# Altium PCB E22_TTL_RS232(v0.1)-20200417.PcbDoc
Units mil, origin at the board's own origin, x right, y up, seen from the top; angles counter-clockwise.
Board outline 1576 x 2223 mil, 2 copper layers (TopLayer, BottomLayer); 30 components, 23 nets, 110 pads, 426 vias.
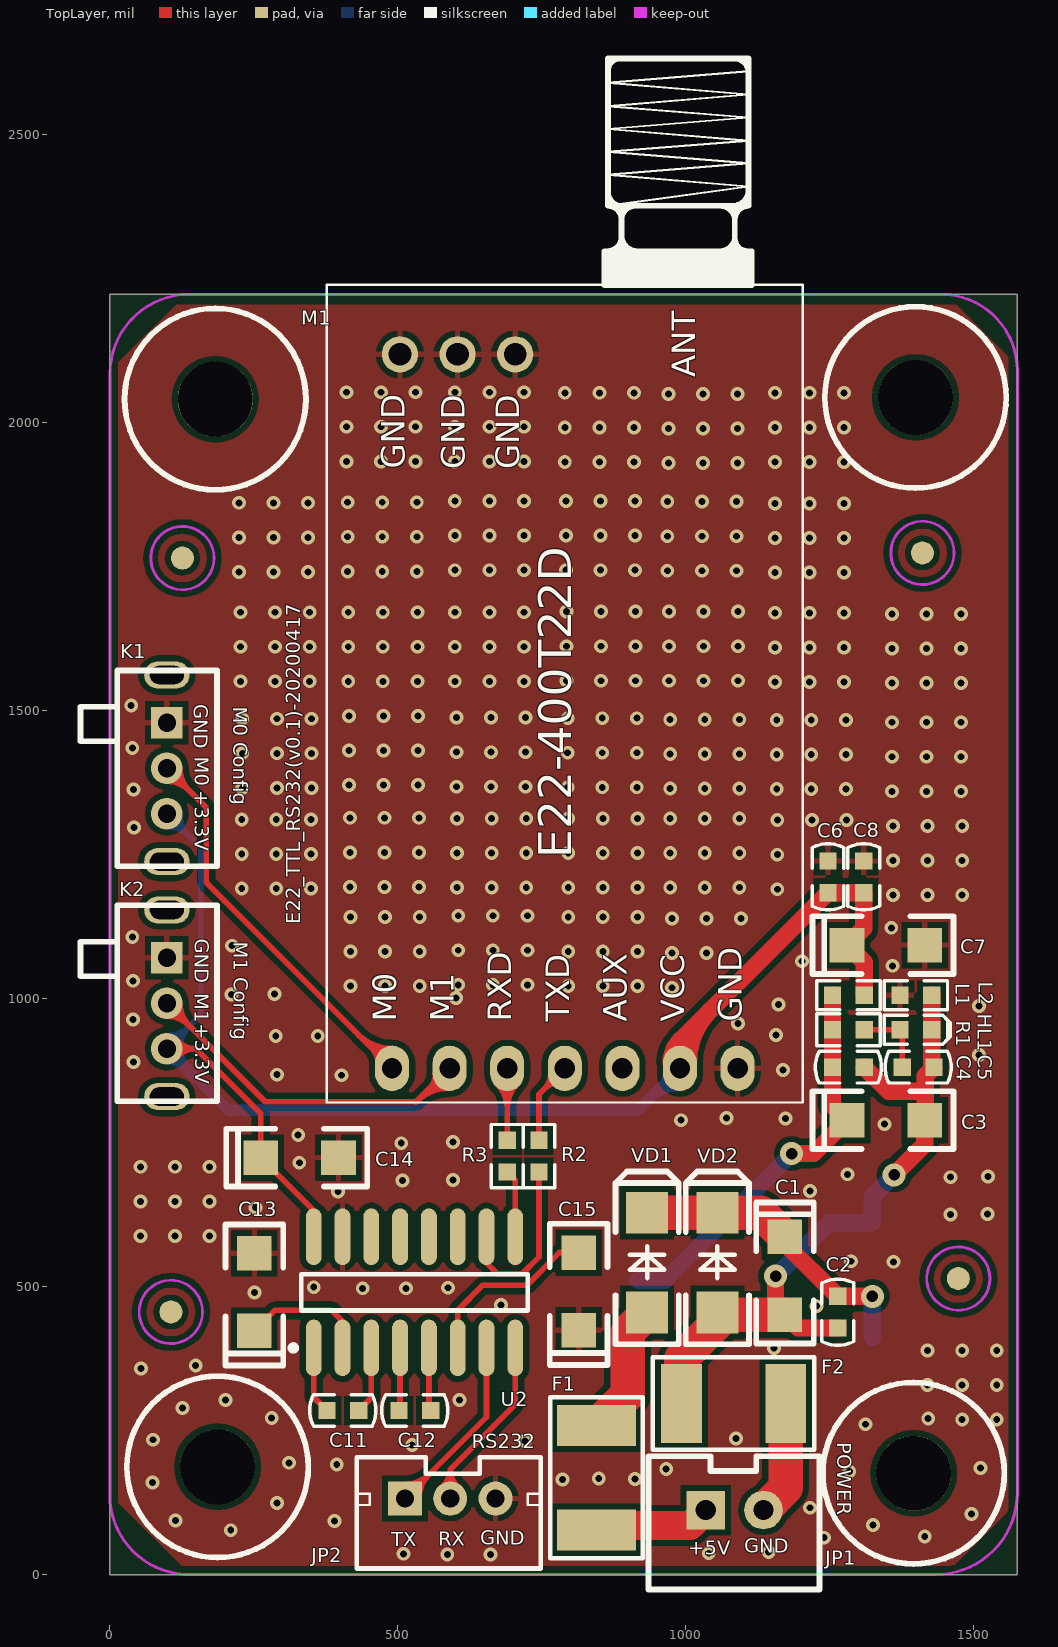
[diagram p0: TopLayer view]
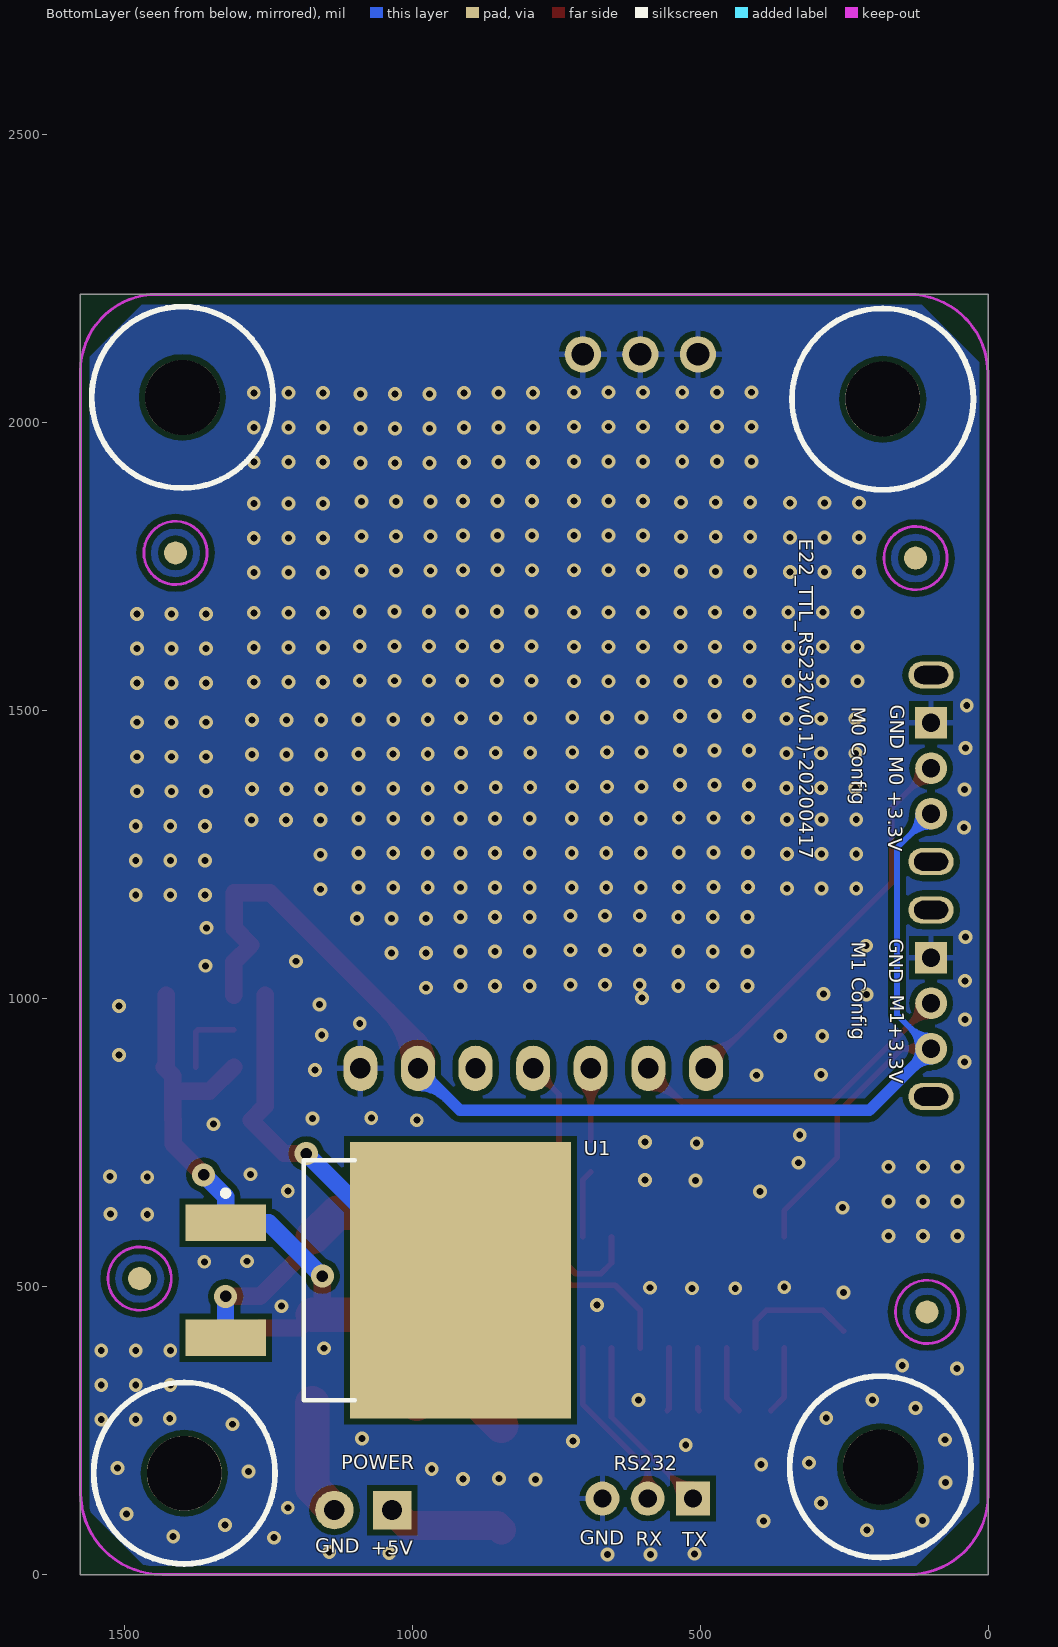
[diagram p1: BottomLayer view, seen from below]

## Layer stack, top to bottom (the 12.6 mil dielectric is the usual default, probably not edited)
TopLayer: signal copper 1.4
Dielectric: core 12.6, FR-4, Dk 4.8
BottomLayer: signal copper 1.4

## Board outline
0,0 1575,0 1576,0 1576,2221 1576,2223 0,2223 0,0

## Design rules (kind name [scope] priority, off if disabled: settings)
Clearance Clearance_2 [InNet('RF_IN') vs InNet('GND')] p1: gap=19.68
Clearance [All] p2: gap=10
Clearance Clearance_1 [All] p3: gap=10
ComponentClearance [All] p1 off: gap=10 collisioncheckmode=3 verticalgap=10 showdistances=FALSE
FabricationTestPointUsage TestPointUsage [All] p1: valid=0 allowmultiple=FALSE
FabricationTestpoint Testpoint [(IsPad And (OnTopLayer Or OnBottomLayer))] p1: side=3 testpointundercomponent=TRUE minsize=40 maxsize=100 preferedsize=60 minholesize=20 maxholesize=40 preferedholesize=32 testpointgrid=1 allowsidetop=TRUE allowsidebottom=TRUE usegrid=TRUE gridtolerance=0.01
HoleSize [All] p1: absolutevalues=TRUE maxlimit=200 minlimit=1 maxpercent=80.000 minpercent=20.000
PolygonConnect [IsVia] p1: connectstyle=Direct reliefconductorwidth=10 reliefentries=4 polygonreliefangle="90 Angle"
PolygonConnect PolygonConnect_via [All] p2 off: connectstyle=Relief reliefconductorwidth=10 reliefentries=4 polygonreliefangle="90 Angle"
RoomDefinition E22_TTL_RS232(v0.1)-20200417 [InComponentClass('E22_TTL_RS232(v0.1)-20200417')] p1: confinementstyle=ConfineIn formatcopy=TRUE lockcomponents=FALSE outline -14648,-34893 -12648,-34893 -12648,-33893 -14648,-33893
RoutingVias [All] p1: holewidth=15.75 width=31.5 viastyle="Through Hole" minholewidth=11.81 minwidth=23.62 maxholewidth=19.68 maxwidth=39.37
ShortCircuit [All] p1 off: allowed=FALSE
SilkscreenOverComponentPads [All] p1: minsilkscreentomaskgap=10
SolderMaskExpansion [All] p1: expansion=4
Width [All] p1: maxlimit=100 minlimit=5 preferedwidth=10
22 further rules are at their usual default settings.

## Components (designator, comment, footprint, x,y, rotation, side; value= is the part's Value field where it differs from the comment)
C1 "10uF/25V/5%" C1206-1 1172.23,586.23 r270 top
C2 "100nF/25V/5%" C0603 1264,428 r90 top
C3 "10uF/25V/5%" C1206-1 1280,789 r0 top
C4 "100nF/25V/5%" C0603 1310,881 r180 top
C5 "100nF/25V/5%" C0603 1376,881 r0 top
C6 "100nF/25V/5%" C0603 1247,1239 r270 top
C7 "10uF/25V/5%" C1206-1 1280,1093 r0 top
C8 "100nF/25V/5%" C0603 1309,1239 r270 top
C11 "100nF/25V/5%" C0603 432,285 r180 top
C12 "100nF/25V/5%" C0603 502,285 r0 top
C13 "100nF/25V/5%" C1206-1 251,423 r90 top
C14 "100nF/25V/5%" C1206-1 262,724 r0 top
C15 "100nF/25V/5%" C1206-1 814,424 r90 top
F1 "6V/500mA" F1812 845,168 r90 top
F2 "6V/500mA" F1812 1083,297 r180 top
HL1 "LED蓝灯" LED0603 1372,946 r0 top
JP1 "供电电源" XH2.54-LI-2P 1085,112 r0 top
JP2 "RS232串口" PH2.0-LI-3P 591,132 r0 top locked
K1 "M0选择" SK-12D07 99,1400 r270 top locked
K2 "M1选择" SK-12D07 99,992 r270 top locked
L1 "10uH/5%" L0603 1255,1006 r0 top
L2 "10uH/5%" L0603 1427,1006 r180 top
M1 "E22-400T22D" E22-400T22D 490,879 r90 top locked
R1 "2K/5%" R0603 1255,946 r0 top
R2 "33R/5%" R0603 745,699 r90 top
R3 "33R/5%" R0603 690,699 r90 top
U1 "AMS1117-3.3" D2PAK 1070,511 r180 bottom
U2 "MAX3232CSE" NSO16_M 529,490 r90 top
VD1 "1N5408" SMA_DO-214AC 933,455 r90 top
VD2 "1N4007" SMA_DO-214AC 1055,455 r90 top

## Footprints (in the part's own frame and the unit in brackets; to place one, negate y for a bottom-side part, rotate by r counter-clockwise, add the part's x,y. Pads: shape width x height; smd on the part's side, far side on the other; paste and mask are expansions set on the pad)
C0603 [mil]
  rect 30x30 smd: 1(0,0) 2(55,0)
  silkscreen extent -30,-28 85,28
C1206-1 [mil] "C1206封装钽电容"
  rect 60x60 smd: 1(0,0) 2(135,0)
  silkscreen extent -60,-50 185,50
D2PAK [mm] "D2-PAK, 3-Pads, Body 9.0x10.6mm (max), IPC Medium Density"
  rect 3.55x1.6 smd: 1(-6.45,2.54) 3(-6.45,-2.54)
  rect 9.75x12.2 smd: 2(3.9,0)
  silkscreen extent -6.58,-5.3 -0.75,5.3, body extent -3,-5.28 6,5.28, height 4.56
E22-400T22D [mm]
  oval 2x1.5 hole 0.9: 1(0,0) 2(0,-2.54) 3(0,-5.08) 4(0,-7.62) 5(0,-10.16) 6(0,-12.7) 7(0,-15.24)
  round 1.6 hole 1: 8(31.49,-5.43) 9(31.49,-2.89) 10(31.49,-0.35)
  silkscreen extent -1.51,-18.12 44.54,2.88
F1812 [mm]
  rect 1.8x3.5 smd: 1(-2.3,0) 2(2.3,0)
  silkscreen extent -3.56,-2.03 3.56,2.03
L0603 [mil] "L0603封装电感"
  rect 30x30 smd: 1(0,0) 2(55,0)
  silkscreen extent -28,-25 82,25
LED0603 [mil]
  rect 30x30 smd: A(0,0) K(55,0)
  silkscreen extent -28,-25 87,25
NSO16_M [mm] "SOIC, 16-Leads, Body 9.9x3.9mm, Pitch 1.27mm, IPC Low Density"
  oval 2.5x0.7 smd: 1(-2.45,4.445) 2(-2.45,3.175) 3(-2.45,1.905) 4(-2.45,0.635) 5(-2.45,-0.635) 6(-2.45,-1.905) 7(-2.45,-3.175) 8(-2.45,-4.445) 9(2.45,-4.445) 10(2.45,-3.175) 11(2.45,-1.905) 12(2.45,-0.635) 13(2.45,0.635) 14(2.45,1.905) 15(2.45,3.175) 16(2.45,4.445)
  silkscreen extent -2.57,-5 0.8,5.47, body extent -2,-5 2,5, height 1.75
PH2.0-LI-3P [mm]
  rect 1.5x1.5 hole 0.8: 1(-2,0)
  round 1.5 hole 0.8: 2(0,0) 3(2,0)
  silkscreen extent -4.13,-3.08 4,1.82, body extent -3.95,-3 3.95,1.7, height 6.01
R0603 [mil]
  rect 30x30 smd: 1(0,0) 2(55,0)
  silkscreen extent -28,-28 82,28
SK-12D07 [mm] "3脚2档小型拨动开关"
  oval 1.2x2 hole 0.8 slot 1.5 at 90 deg: 0(-4.115,0) 0(4.115,0)
  rect 1.4x1.4 hole 0.8: 1(-2.007,0)
  round 1.4 hole 0.8: 2(0,0) 3(2.007,0)
  silkscreen extent -4.32,-3.81 4.32,2.21
SMA_DO-214AC [mm]
  rect 1.85x1.85 smd: A(0,0) K(4.4,0)
  silkscreen extent -1.4,-1.4 6.22,1.4
XH2.54-LI-2P [mm]
  rect 1.7x1.7 hole 0.9: 1(-1.27,0)
  round 1.7 hole 0.9: 2(1.27,0)
  silkscreen extent -3.81,-3.51 3.74,2.37, body extent -3.77,-3.3 3.77,2.4, height 7.05

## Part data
C1 C3: library part "Cap Pol1", "钽电容"
C2 C4: library part Cap, "电容"
C5 C6: library part CAP, "电容"
C7 C13 C14 C15: library part ELECTRO1, "钽电容"
C8 C11 C12: library part CAP-SMD, "电容"
F1 F2: library part 保险丝, "自恢复保险丝"
HL1: library part 发光二极管, "发光二极管"
JP1: library part XH2.54-2P/PH2.0-2P, "XH2.54-2P/PH2.0-2P插座"
JP2: library part XH2.54-3P/PH2.0-3P, "PH2.0-3P直插插座"
K1 K2: library part SK-12D07, "SK-12D07：3脚2档小型拨动开关"
L1 L2: library part 电感, "电感"
M1: "E22-400T22D LoRa模块"
R1 R2 R3: library part RES2, "电阻"
U1: library part U_AMS1117, "U_AMS1117稳压芯片"
U2: library part MAX232CSE, "+5V Powered, Multi-Channel RS-232 Driver/Receiver"
VD1 VD2: library part 开关二极管, "开关二极管"

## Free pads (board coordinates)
  round 40 smd far side: 0(106,456) 0(126,1765) 0(1411,1774) 0(1473.31,513.95)
  round 129.92 hole 129.92: 0(183,2041) 0(187.01,187.01) 0(1395.68,176.01) 0(1399,2044)
  round 40 smd: 1(106,456) 1(126,1765) 1(1411,1774) 1(1473.31,513.95)
  round 100 on Bottom Solder: 2(106,456) 2(126,1765) 2(1411,1774) 2(1473.31,513.95)
  round 100 on Top Solder: 3(106,456) 3(126,1765) 3(1411,1774) 3(1473.31,513.95)

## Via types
v1: diameter 24, hole 12, TopLayer to BottomLayer, tented both sides, 422 vias
v2: diameter 40, hole 20, TopLayer to BottomLayer, tented both sides, 4 vias

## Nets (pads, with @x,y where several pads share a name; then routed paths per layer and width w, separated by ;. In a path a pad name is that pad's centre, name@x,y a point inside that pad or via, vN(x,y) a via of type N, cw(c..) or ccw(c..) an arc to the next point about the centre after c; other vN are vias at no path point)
3V3: C6.2 C7.1 C8.2 C14.1 K1.3 K2.3 L1.2 M1.6 U2.16 | length 3284.4
  TopLayer w10: K2.3 149.72,913 ; K2.3@108.33,904.59 cw(c127.23,887.54) 127.23,913 cw(c127.23,938.46) K2.3@108.33,921.41 ; K2.3@115.75,897.89 cw(c149.71,867.28) 149.71,913 ; K2.3@115.75,928.11 ccw(c149.71,958.72) 149.71,913 ; U2.16 354,632 C14.1 262,800.72 149.72,913
  TopLayer w30: M1.6@974.53,888.84 cw(c1029.29,888.84) 990.57,927.57 ; M1.6@979.73,899.11 ccw(c954.93,923.92) 990,923.92 ccw(c1025.07,923.92) M1.6@1000.27,899.11 ; M1.6 990,927 C6.2 C8.2 1309,1122 C7.1 1310,1063 L1.2 ; M1.6@1004.53,888.84 cw(c1131.72,888.84) 1041.78,978.78
  BottomLayer w10: K2.3 158,972 158,1262 K1.3 ; K2.3@99,925.56 ccw(c99,955.88) 120.44,934.44 ccw(c141.88,913) K2.3@111.56,913 ; K2.3@99,935.56 ccw(c99,990.02) 137.51,951.51 ccw(c176.02,913) K2.3@121.56,913 ; K1.3@99,1298.44 cw(c99,1243.98) 137.51,1282.49 cw(c176.02,1321) K1.3@121.56,1321 ; K1.3@99,1308.44 cw(c99,1278.12) 120.44,1299.56 cw(c141.88,1321) K1.3@111.56,1321
  BottomLayer w20: K2.3@99,895.44 cw(c99,853.05) 128.98,883.02 cw(c158.95,913) K2.3@116.56,913 ; K2.3 206,806 917,806 M1.6 ; 939.86,828.86 cw(c990,778.72) M1.6@990,849.63 ; 963.62,852.62 ccw(c947.09,869.16) M1.6@970.47,869.16
3V3A: C3.1 C4.2 L1.1 R1.1 U1.2 | length 706.1
  TopLayer w30: v2(1184,731) 1222,731 C3.1 1255,814 C4.2 R1.1 L1.1
  BottomLayer w30: U1.2 964,511 v2(1184,731)
+5V: C1.1 C2.2 U1.3 VD1.K VD2.K | length 529.9
  TopLayer w30: C1.1 1172.23,574.77 C2.2 v2(1324,483)
  TopLayer w60: VD1.K VD2.K 1130.23,628.23 C1.1
  BottomLayer w30: U1.3 1324,411.06 v2(1324,483)
+5V_IN: F1.1 JP1.1 | length 204.3
  TopLayer w50: F1.1 852.55,85 1008,85 JP1.1
AGND: C1.2 C2.1 C3.2 C4.1 C5.2 F2.2 HL1.K L2.1 U1.1 VD2.A | length 1248.4
  TopLayer w30: v2(1156,518) 1156,467.46 C1.2 1195.46,428 C2.1 ; C4.1 1352,839 1416,839 ; v2(1362,694) 1415,747 C3.2 1416,790 1416,839 ; L2.1 HL1.K 1427,885 C5.2 1416,866 1416,839
  TopLayer w60: F2.2 992.45,374.89 1055,437.44 VD2.A 1058.77,451.23 C1.2
  BottomLayer w30: v2(1156,518) 1249,611 U1.1 1323.94,655.94 v2(1362,694)
DGND: C6.1 C7.2 C8.1 C13.2 C14.2 C15.1 JP2.3 K1.1 K2.1 L2.2 M1.7 M1.8 M1.9 M1.10 U2.15
  other v1: 586,35 661,35 510,36 1040,37 1144,39 1240,64 1415,66 210,77 1325,86 390,93 114,94 1496,105 1216,116 290,124 74,160 786,165 912,166 849,167 1284,179 966,183 1512,185 394,191 311,194 525,225 721,232 75,234 1087,236 1312,261 1480,269 1540,269 1421,271 281,272 126,289 201,303 607,303 1420,329 1480,329 1540,329 54,358 149,363 1420,389 1480,389 1540,389 1153,393 1227,466 679,468 251,490 439,497 514,497 587,498 354,499 1361,543 1287,544 53,588 113,588 173,588 1460,625 1524,626 253,637 53,648 113,648 173,648 396,665 1216,666 508,684 596,685 1460,690 1525,691 1281,695 53,708 113,708 173,708 329,715 506,749 596,751 327,763 1345,782 992,789 1173,792 1071,793 402,867 290,868 1169,876 41,890 1509,902 288,935 361,935 1157,937 1091,957 40,964 1509,987 1161,990 601,1001 211,1007 286,1008 976,1019 418,1022 478,1022 538,1022 796,1022 856,1022 916,1022 605,1024 665,1024 725,1024 40,1031 1359,1057 1202,1065 976,1079 1036,1079 418,1082 478,1082 538,1082 796,1082 856,1082 916,1082 605,1084 665,1084 725,1084 212,1092 39,1107 1357,1123 976,1139 1036,1139 1096,1139 418,1142 478,1142 538,1142 796,1142 856,1142 916,1142 605,1144 665,1144 725,1144 1360,1180 1420,1180 1480,1180 1159,1190 229,1191 289,1191 349,1191 603,1193 663,1193 723,1193 796,1193 856,1193 916,1193 973,1193 1033,1193 1093,1193 417,1194 477,1194 537,1194 1360,1240 1420,1240 1480,1240 1159,1250 229,1251 289,1251 349,1251 603,1253 663,1253 723,1253 796,1253 856,1253 916,1253 973,1253 1033,1253 1093,1253 417,1254 477,1254 537,1254 42,1297 1360,1300 1420,1300 1480,1300 1159,1310 1219,1310 1279,1310 229,1311 289,1311 349,1311 603,1313 663,1313 723,1313 796,1313 856,1313 916,1313 973,1313 1033,1313 1093,1313 417,1314 477,1314 537,1314 1358,1360 1418,1360 1478,1360 41,1363 1158,1364 1218,1364 1278,1364 973,1365 1033,1365 1093,1365 230,1366 290,1366 350,1366 795,1367 855,1367 915,1367 602,1368 662,1368 722,1368 415,1371 475,1371 535,1371 1358,1420 1418,1420 1478,1420 1158,1424 1218,1424 1278,1424 973,1425 1033,1425 1093,1425 230,1426 290,1426 350,1426 795,1427 855,1427 915,1427 602,1428 662,1428 722,1428 415,1431 475,1431 535,1431 39,1435 1358,1480 1418,1480 1478,1480 1158,1484 1218,1484 1278,1484 973,1485 1033,1485 1093,1485 230,1486 290,1486 350,1486 795,1487 855,1487 915,1487 602,1488 662,1488 722,1488 415,1491 475,1491 535,1491 37,1509 1358,1548 1418,1548 1478,1548 1155,1550 1215,1550 1275,1550 227,1551 287,1551 347,1551 414,1551 474,1551 534,1551 599,1551 659,1551 719,1551 793,1552 853,1552 913,1552 971,1552 1031,1552 1091,1552 1358,1608 1418,1608 1478,1608 1155,1610 1215,1610 1275,1610 227,1611 287,1611 347,1611 414,1611 474,1611 534,1611 599,1611 659,1611 719,1611 793,1612 853,1612 913,1612 971,1612 1031,1612 1091,1612 1358,1668 1418,1668 1478,1668 1155,1670 1215,1670 1275,1670 227,1671 287,1671 347,1671 414,1671 474,1671 534,1671 599,1671 659,1671 719,1671 793,1672 853,1672 913,1672 971,1672 1031,1672 1091,1672 1155,1740 1215,1740 1275,1740 224,1741 284,1741 344,1741 413,1742 473,1742 533,1742 968,1743 1028,1743 1088,1743 599,1744 659,1744 719,1744 792,1744 852,1744 912,1744 1155,1800 1215,1800 1275,1800 224,1801 284,1801 344,1801 413,1802 473,1802 533,1802 968,1803 1028,1803 1088,1803 599,1804 659,1804 719,1804 792,1804 852,1804 912,1804 1155,1860 1215,1860 1275,1860 224,1861 284,1861 344,1861 413,1862 473,1862 533,1862 968,1863 1028,1863 1088,1863 599,1864 659,1864 719,1864 792,1864 852,1864 912,1864 970,1930 1030,1930 1090,1930 790,1932 850,1932 910,1932 1155,1932 1215,1932 1275,1932 411,1933 471,1933 531,1933 599,1933 659,1933 719,1933 970,1990 1030,1990 1090,1990 790,1992 850,1992 910,1992 1155,1992 1215,1992 1275,1992 411,1993 471,1993 531,1993 599,1993 659,1993 719,1993 970,2050 1030,2050 1090,2050 790,2052 850,2052 910,2052 1155,2052 1215,2052 1275,2052 411,2053 471,2053 531,2053 599,2053 659,2053 719,2053
GND: F2.1 JP1.2 | length 201
  TopLayer w60: JP1.2 1173.55,150.55 F2.1
M0: K1.2 M1.1 | length 955.4
  TopLayer w10: K1.2@99,1377.44 cw(c99,1322.98) 137.51,1361.49 cw(c176.02,1400) K1.2@121.56,1400 ; K1.2@99,1387.44 cw(c99,1357.12) 120.44,1378.56 cw(c141.88,1400) K1.2@111.56,1400 ; K1.2 167.31,1331.69 167.31,1201.69 M1.1 ; 431.33,937.67 ccw(c490,996.35) M1.1@490,913.37 ; 448.4,920.6 ccw(c490,962.2) M1.1@490,903.37 ; 455.09,913.91 cw(c430.02,888.84) M1.1@465.47,888.84
M1: K2.2 M1.2 | length 858.3
  TopLayer w10: K2.2@99,969.44 cw(c99,914.98) 137.51,953.49 cw(c176.02,992) K2.2@121.56,992 ; K2.2@99,979.44 cw(c99,949.12) 120.44,970.56 cw(c141.88,992) K2.2@111.56,992 ; K2.2 270,821 532,821 M1.2 ; 531.33,820.33 cw(c590,761.65) M1.2@590,844.63 ; 548.4,837.4 cw(c590,795.8) M1.2@590,854.63 ; 555.09,844.09 ccw(c530.02,869.16) M1.2@565.47,869.16
NetC5_1: C5.1 HL1.A R1.2 | length 128.7
  TopLayer w10: R1.2 HL1.A 1376,942 C5.1
NetC11_1: C11.1 U2.3 | length 117.7
  TopLayer w10: C11.1 454,307 U2.3
NetC11_2: C11.2 U2.1 | length 118.1
  TopLayer w10: U2.1 354,308 C11.2
NetC12_1: C12.1 U2.4 | length 109.4
  TopLayer w10: C12.1 504,287 U2.4
NetC12_2: C12.2 U2.5 | length 109.8
  TopLayer w10: U2.5 554,288 C12.2
NetC13_1: C13.1 U2.2 | length 222.2
  TopLayer w10: C13.1 287,459 385,459 404,440 U2.2
NetC15_2: C15.2 U2.6 | length 316.9
  TopLayer w10: U2.6 604,459 647.24,502.24 724.2,502.24 780.96,559 C15.2
NetF1_2: F1.2 VD1.A | length 232.9
  TopLayer w60: F1.2 899.22,312.78 899.22,421.22 VD1.A
NetR2_1: R2.1 U2.10 | length 303.9
  TopLayer w10: U2.10 654,541 672.76,522.24 715.92,522.24 745,551.32 R2.1
NetR3_1: R3.1 U2.9 | length 118.3
  TopLayer w10: R3.1 704,685 U2.9
RS232_RX: JP2.2 U2.8 | length 422.6
  TopLayer w10: JP2.2@575.85,151.29 ccw(c551.37,182.45) 591,182.45 ; JP2.2@582.03,143.42 ccw(c567.53,161.88) 591,161.88 ccw(c614.47,161.88) JP2.2@599.97,143.42 ; JP2.2 591,182.46 ; JP2.2@606.15,151.29 cw(c630.63,182.45) 591,182.45 ; U2.8 704,295.46 591,182.46
RS232_TX: JP2.1 U2.7 | length 468.4
  TopLayer w10: JP2.1 654,273.74 U2.7 ; JP2.1@512.26,146.53 ccw(c512.26,181.6) 537.06,156.8 ccw(c561.86,132) JP2.1@526.79,132 ; JP2.1@512.26,156.53 ccw(c512.26,215.74) 554.13,173.87 ccw(c596,132) JP2.1@536.79,132
TTL_RX: M1.3 R3.2 | length 273.1
  TopLayer w10: M1.3@672.66,851.81 cw(c630.79,809.94) 690,809.94 cw(c749.21,809.94) M1.3@707.34,851.81 ; M1.3@679.73,858.89 cw(c654.93,834.08) 690,834.08 cw(c725.07,834.08) M1.3@700.27,858.89 ; R3.2 M1.3
TTL_TX: M1.4 R2.2 | length 208.3
  TopLayer w10: R2.2 745,834 M1.4 ; 754.37,843.37 cw(c782.73,815.02) M1.4@788.07,854.76 ; 755.09,844.09 ccw(c730.02,869.16) M1.4@765.47,869.16
pads on no net: K1.0 K2.0 M1.5 U2.11 U2.12 U2.13 U2.14

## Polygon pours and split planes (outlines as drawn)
DGND on BottomLayer "BottomLayer-No Net" (solid, pour order 1000): 245,15 1465,15 1560,110 1560,2115 1470,2205 115,2205 15,2105 15,125 125,15 245,15
DGND on TopLayer "BottomLayer-No Net" (solid, pour order 1001): 245,15 1465,15 1560,110 1560,2115 1470,2205 115,2205 15,2105 15,125 125,15 245,15

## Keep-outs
TopLayer:
  circle w5: c106,456 r55
  circle w5: c1473.31,513.95 r55
  circle w5: c1411,1774 r55
  circle w5: c126,1765 r55
BottomLayer:
  circle w5: c106,456 r55
  circle w5: c1473.31,513.95 r55
  circle w5: c1411,1774 r55
  circle w5: c126,1765 r55
KeepOutLayer:
  lines w5: 0,2085.2 0,137.8 ccw(c137.8,137.8) 140.05,0.02 615,0 1433.98,0 ccw(c1433.98,141.83) 1575.82,141.83 1575.82,2090 ; 0.2,2085.2 cw(c138,2085.2) 138,2223 1442.99,2223.01 cw(c1442.99,2090) 1576,2090

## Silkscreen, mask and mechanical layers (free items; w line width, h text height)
TopOverlay:
  circle w10: c187.01,187.01 r157.48
  circle w10: c1395.68,176.01 r157.48
  circle w10: c183,2041 r157.48
  circle w10: c1399,2044 r157.48
  text "GND" at 146,1511 h25 r270
  text "M0 Config" at 214,1507 h25 r270
  text "M0" at 147,1420 h25 r270
  text "+3.3V" at 147,1362 h25 r270
  text "E22_TTL_RS232(v0.1)-20200417" at 331,1129 h25 r90
  text "GND" at 147,1104 h25 r270
  text "M1 Config" at 215,1099 h25 r270
  text "M1" at 147,1009 h25 r270
  text "+3.3V" at 148,957 h25 r270
  text "POWER" at 1263,230 h25 r270
  text "RS232" at 628.04,219.5 h25
  text "GND" at 643,52 h25
  text "RX" at 570,50 h25
  text "TX" at 489,49 h25
  text "GND" at 1102,38 h25
  text "+5V" at 1004,34 h25
BottomOverlay:
  circle w10: c1395.68,176.01 r157.48
  circle w10: c187.01,187.01 r157.48
  circle w10: c183,2041 r157.48
  circle w10: c1399,2044 r157.48
  text "E22_TTL_RS232(v0.1)-20200417" at 328,1799 h25 r90
  text "GND" at 170,1510 h25 r90
  text "M0 Config" at 237,1507 h25 r90
  text "M0" at 172,1421 h25 r90
  text "+3.3V" at 173,1361 h25 r90
  text "GND" at 172,1104 h25 r90
  text "M1 Config" at 237,1099 h25 r90
  text "M1" at 170,1007 h25 r90
  text "+3.3V" at 172,958 h25 r90
  text "POWER" at 1123,183 h25
  text "RS232" at 650,181 h25
  text "GND" at 709,52 h25
  text "RX" at 612,50 h25
  text "TX" at 531,49 h25
  text "GND" at 1168,38 h25
  text "+5V" at 1072,34 h25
